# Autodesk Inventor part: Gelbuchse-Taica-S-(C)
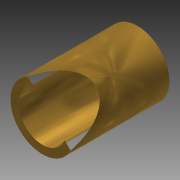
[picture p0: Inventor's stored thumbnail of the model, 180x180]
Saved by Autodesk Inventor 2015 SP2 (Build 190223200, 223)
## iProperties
Created: 2014-12
Part Number: Gelbuchse-Taica-S-(C)
Material: Messing, weicher Gelbton
Document SubType Name: Modeling
Designer: Hübner
Density: 1 g/cm^3
Appearance: Messing - satiniert
Author: Hübner
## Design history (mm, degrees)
sketch "Skizze1"
  geometry: C1 r 1.5 at (0, 0); C2 r 2 at (0, 0); 1 further point
  constraints: 2 centre point, 2 coincident
  dimensions: "d0" = 3 diameter of C1; "d1" = 4 diameter of C2
extrude "Extrusion1" new body sketch "Skizze1" distance "d2" = 6; taper "d3" = 0 deg
node "Volumenkörper1"
